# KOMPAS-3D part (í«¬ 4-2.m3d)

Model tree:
1. Эскиз:1
2. Операция выдавливания:1
     Расстояние 1 = 3
3. Эскиз:2
4. Операция выдавливания:2
     Расстояние 1 = 78
5. Эскиз:3
6. Операция выдавливания:3
     Расстояние 1 = 3
7. Эскиз:4
8. Операция выдавливания:4
     Расстояние 1 = 4
9. Эскиз:5
10. Операция выдавливания:5
     Расстояние 1 = 4
11. Эскиз:6
12. Вырезать элемент выдавливания:1
     Расстояние 1 = 100
